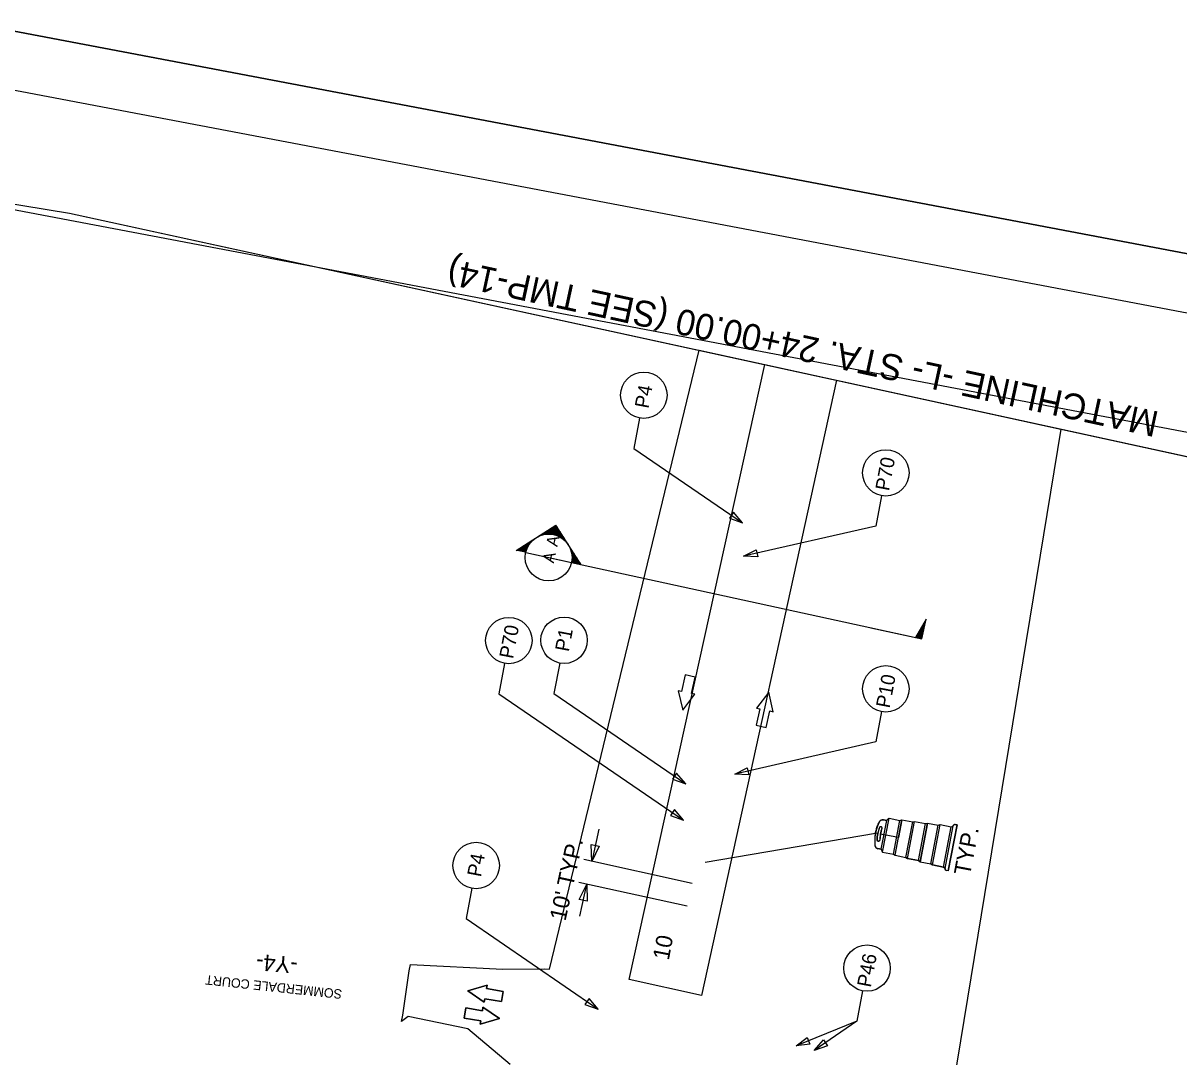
# Model space of a CAD drawing. Extents: x 1615680 to 1619687, y 899305 to 902270.
# Drawn here: x 1616156.6 to 1616649.2, y 900701 to 901141.7 of the extents above; entities that cross this region are included whole.
import ezdxf

# ---------------------------------------------------------------- set-up
doc = ezdxf.new("R2010")
doc.units = 0
for name, color, linetype in [('Default', 7, 'Continuous'), ('Prop Conc 2ft 6in Curb and Gutter', 7, 'Continuous'), ('Prop Conc 4in Sidewalk', 7, 'Continuous'), ('Prop Conc 5in Monolithic Keyed In Island', 7, 'Continuous'), ('Prop Conc Valley Gutter', 7, 'Continuous'), ('Prop Lane Arrow CELL', 7, 'Continuous'), ('Prop Mkg Solid Yel Skip RT Rpm 80ft', 7, 'Continuous'), ('Prop Shade Light', 7, 'Continuous'), ('Scratch_Level_5', 7, 'Continuous'), ('Scratch_Level_7', 7, 'Continuous'), ('Scratch_Level_8', 7, 'Continuous'), ('Stage 1', 7, 'Continuous'), ('Stage 5', 7, 'Continuous')]:
    doc.layers.add(name, color=color, linetype=linetype)

msp = doc.modelspace()

# ---------------------------------------------------------------- linework, layer by layer
at = {"layer": 'Default'}
for p, q in [((1616366.8, 900916.91), (1616383.64, 900927.73)), ((1616380.01, 900925.34), (1616379.7, 900923.91)), ((1616380.26, 900925.5), (1616379.91, 900923.91)), ((1616380.5, 900925.66), (1616380.12, 900923.91)), ((1616380.75, 900925.82), (1616380.34, 900923.91)), ((1616381, 900925.98), (1616380.55, 900923.91)), ((1616381.25, 900926.14), (1616380.76, 900923.91)), ((1616381.5, 900926.29), (1616380.98, 900923.91)), ((1616381.74, 900926.45), (1616381.19, 900923.91)), ((1616381.99, 900926.61), (1616381.4, 900923.89)), ((1616382.24, 900926.77), (1616381.61, 900923.87)), ((1616382.49, 900926.93), (1616381.81, 900923.85)), ((1616382.73, 900927.09), (1616382.02, 900923.82)), ((1616382.98, 900927.25), (1616382.23, 900923.8)), ((1616383.23, 900927.41), (1616382.44, 900923.77)), ((1616383.48, 900927.57), (1616382.65, 900923.75)), ((1616383.68, 900927.52), (1616382.85, 900923.72)), ((1616383.84, 900927.27), (1616383.06, 900923.68)), ((1616384, 900927.03), (1616383.26, 900923.63)), ((1616384.16, 900926.78), (1616383.46, 900923.59)), ((1616394.5, 900910.82), (1616383.64, 900927.73)), ((1616384.32, 900926.53), (1616383.67, 900923.54)), ((1616384.48, 900926.29), (1616383.87, 900923.5)), ((1616384.64, 900926.04), (1616384.07, 900923.46)), ((1616384.8, 900925.8), (1616384.25, 900923.29)), ((1616384.96, 900925.55), (1616384.44, 900923.17)), ((1616385.12, 900925.3), (1616384.63, 900923.07)), ((1616372.28, 900920.4), (1616372.01, 900919.16)), ((1616372.53, 900920.57), (1616372.32, 900919.6)), ((1616372.78, 900920.73), (1616372.63, 900920.03)), ((1616373.03, 900920.89), (1616372.92, 900920.37)), ((1616373.28, 900921.05), (1616373.19, 900920.66)), ((1616373.52, 900921.21), (1616373.47, 900920.95)), ((1616377.28, 900923.59), (1616377.24, 900923.4)), ((1616377.53, 900923.75), (1616377.48, 900923.51)), ((1616377.78, 900923.91), (1616377.72, 900923.62)), ((1616378.03, 900924.07), (1616377.94, 900923.69)), ((1616378.27, 900924.23), (1616378.17, 900923.73)), ((1616378.52, 900924.39), (1616378.39, 900923.77)), ((1616378.77, 900924.54), (1616378.61, 900923.82)), ((1616379.02, 900924.7), (1616378.83, 900923.86)), ((1616379.26, 900924.86), (1616379.06, 900923.91)), ((1616379.51, 900925.02), (1616379.27, 900923.91)), ((1616379.76, 900925.18), (1616379.48, 900923.91)), ((1616385.28, 900925.06), (1616384.82, 900922.97)), ((1616385.44, 900924.81), (1616385.01, 900922.88)), ((1616385.6, 900924.57), (1616385.21, 900922.78)), ((1616385.76, 900924.32), (1616385.4, 900922.68)), ((1616385.91, 900924.07), (1616385.59, 900922.58)), ((1616386.07, 900923.83), (1616385.78, 900922.47)), ((1616386.23, 900923.58), (1616385.96, 900922.33)), ((1616386.39, 900923.34), (1616386.14, 900922.19)), ((1616386.55, 900923.09), (1616386.33, 900922.05)), ((1616386.71, 900922.84), (1616386.51, 900921.91)), ((1616386.87, 900922.6), (1616386.69, 900921.77)), ((1616387.03, 900922.35), (1616386.88, 900921.63)), ((1616387.19, 900922.11), (1616387.06, 900921.49)), ((1616387.35, 900921.86), (1616387.24, 900921.35)), ((1616387.51, 900921.61), (1616387.42, 900921.2)), ((1616387.67, 900921.37), (1616387.6, 900921.06)), ((1616387.83, 900921.12), (1616387.78, 900920.91)), ((1616367.07, 900917.03), (1616367.03, 900916.86)), ((1616367.32, 900917.19), (1616367.24, 900916.81)), ((1616367.57, 900917.35), (1616367.44, 900916.77)), ((1616367.82, 900917.51), (1616367.64, 900916.73)), ((1616368.06, 900917.67), (1616367.85, 900916.68)), ((1616368.31, 900917.83), (1616368.05, 900916.64)), ((1616368.56, 900917.99), (1616368.26, 900916.59)), ((1616368.81, 900918.15), (1616368.46, 900916.55)), ((1616369.06, 900918.31), (1616368.66, 900916.5)), ((1616369.3, 900918.48), (1616368.87, 900916.46)), ((1616369.55, 900918.64), (1616369.07, 900916.42)), ((1616369.8, 900918.8), (1616369.27, 900916.37)), ((1616370.05, 900918.96), (1616369.48, 900916.33)), ((1616370.3, 900919.12), (1616369.68, 900916.28)), ((1616370.55, 900919.28), (1616369.88, 900916.24)), ((1616370.79, 900919.44), (1616370.09, 900916.19)), ((1616371.04, 900919.6), (1616370.29, 900916.15)), ((1616371.29, 900919.76), (1616370.49, 900916.11)), ((1616371.54, 900919.92), (1616370.7, 900916.06)), ((1616370.8, 900915.99), (1616390.34, 900911.73)), ((1616370.8, 900915.98), (1616388.4, 900912.15)), ((1616371.79, 900920.08), (1616371.25, 900917.61)), ((1616372.03, 900920.24), (1616371.68, 900918.61)), ((1616390.15, 900917.42), (1616390.1, 900917.18)), ((1616390.31, 900917.17), (1616390.24, 900916.84)), ((1616390.47, 900916.92), (1616390.36, 900916.43)), ((1616390.63, 900916.68), (1616390.49, 900916.02)), ((1616390.79, 900916.43), (1616390.59, 900915.51)), ((1616391.42, 900915.43), (1616390.62, 900911.75)), ((1616391.27, 900915.68), (1616390.68, 900912.97)), ((1616390.95, 900916.18), (1616390.69, 900914.97)), ((1616391.11, 900915.93), (1616390.78, 900914.43)), ((1616390.34, 900911.73), (1616539.62, 900879.2)), ((1616391.58, 900915.18), (1616390.83, 900911.7)), ((1616391.74, 900914.93), (1616391.03, 900911.65)), ((1616391.9, 900914.68), (1616391.23, 900911.61)), ((1616392.06, 900914.43), (1616391.43, 900911.56)), ((1616392.22, 900914.18), (1616391.64, 900911.51)), ((1616392.38, 900913.93), (1616391.84, 900911.46)), ((1616392.54, 900913.68), (1616392.04, 900911.42)), ((1616392.69, 900913.43), (1616392.25, 900911.37)), ((1616392.85, 900913.18), (1616392.45, 900911.32)), ((1616393.01, 900912.93), (1616392.65, 900911.28)), ((1616393.17, 900912.69), (1616392.85, 900911.23)), ((1616393.33, 900912.44), (1616393.06, 900911.18)), ((1616393.49, 900912.19), (1616393.26, 900911.14)), ((1616393.65, 900911.94), (1616393.46, 900911.09)), ((1616393.81, 900911.69), (1616393.67, 900911.04)), ((1616393.97, 900911.44), (1616393.87, 900910.99)), ((1616394.12, 900911.19), (1616394.07, 900910.95)), ((1616541.43, 900887.52), (1616536.99, 900879.78)), ((1616539.62, 900879.2), (1616541.43, 900887.52)), ((1616541.04, 900885.79), (1616540.56, 900885.9)), ((1616541.09, 900885.99), (1616540.67, 900886.09)), ((1616541.13, 900886.2), (1616540.78, 900886.27)), ((1616541.18, 900886.4), (1616540.89, 900886.46)), ((1616541.22, 900886.61), (1616541, 900886.65)), ((1616541.26, 900886.81), (1616541.1, 900886.84)), ((1616541.31, 900887.01), (1616541.21, 900887.03)), ((1616517.94, 900883.93), (1616539.62, 900879.2)), ((1616539.89, 900880.5), (1616537.75, 900880.97)), ((1616539.93, 900880.7), (1616537.86, 900881.16)), ((1616539.98, 900880.91), (1616537.96, 900881.35)), ((1616540.02, 900881.11), (1616538.07, 900881.54)), ((1616540.07, 900881.31), (1616538.18, 900881.72)), ((1616540.11, 900881.52), (1616538.29, 900881.91)), ((1616540.16, 900881.72), (1616538.4, 900882.1)), ((1616540.2, 900881.92), (1616538.51, 900882.29)), ((1616540.24, 900882.13), (1616538.61, 900882.48)), ((1616540.29, 900882.33), (1616538.72, 900882.67)), ((1616540.33, 900882.53), (1616538.83, 900882.86)), ((1616540.38, 900882.74), (1616538.94, 900883.05)), ((1616540.42, 900882.94), (1616539.05, 900883.24)), ((1616540.47, 900883.14), (1616539.16, 900883.43)), ((1616540.51, 900883.35), (1616539.26, 900883.62)), ((1616540.56, 900883.55), (1616539.37, 900883.81)), ((1616540.6, 900883.76), (1616539.48, 900884)), ((1616540.64, 900883.96), (1616539.59, 900884.19)), ((1616540.69, 900884.16), (1616539.7, 900884.38)), ((1616540.73, 900884.37), (1616539.81, 900884.57)), ((1616540.78, 900884.57), (1616539.91, 900884.76)), ((1616540.82, 900884.77), (1616540.02, 900884.95)), ((1616540.87, 900884.98), (1616540.13, 900885.14)), ((1616540.91, 900885.18), (1616540.24, 900885.33)), ((1616540.95, 900885.38), (1616540.35, 900885.52)), ((1616541, 900885.59), (1616540.45, 900885.71)), ((1616539.62, 900879.28), (1616537.1, 900879.83)), ((1616539.67, 900879.48), (1616537.21, 900880.02)), ((1616539.71, 900879.69), (1616537.31, 900880.21)), ((1616539.76, 900879.89), (1616537.42, 900880.4)), ((1616539.8, 900880.09), (1616537.53, 900880.59)), ((1616539.85, 900880.3), (1616537.64, 900880.78)), ((1616511.96, 900716.19), (1616493.77, 900703.78))]:
    msp.add_line(p, q, dxfattribs=at)
for points in [[(1616419.31, 900973.34), (1616416.85, 900960.4), (1616463.25, 900928.63)], [(1616522.44, 900940.23), (1616519.98, 900927.29), (1616463.69, 900914.4)], [(1616361.77, 900868.76), (1616359.32, 900855.81), (1616438.12, 900801.85)], [(1616385.29, 900868.87), (1616382.83, 900855.93), (1616439.03, 900817.45)], [(1616522.45, 900848.18), (1616520, 900835.24), (1616459.86, 900821.46)], [(1616347.84, 900772.86), (1616345.38, 900759.92), (1616401.72, 900721.34)], [(1616514.41, 900729.13), (1616511.96, 900716.19), (1616486, 900705.66)]]:
    msp.add_lwpolyline(points, dxfattribs=at)
for points in [[(1616457.59, 900930.62), (1616463.25, 900928.63), (1616459.34, 900933.18)], [(1616469.69, 900914.18), (1616463.69, 900914.4), (1616468.99, 900917.2)], [(1616433.37, 900819.44), (1616439.03, 900817.45), (1616435.12, 900822)], [(1616465.86, 900821.24), (1616459.86, 900821.46), (1616465.16, 900824.27)], [(1616432.46, 900803.85), (1616438.12, 900801.85), (1616434.22, 900806.41)], [(1616396.06, 900723.33), (1616401.72, 900721.34), (1616397.81, 900725.9)], [(1616491.95, 900706.4), (1616486, 900705.66), (1616490.78, 900709.28)], [(1616499.43, 900705.76), (1616493.77, 900703.78), (1616497.68, 900708.33)]]:
    msp.add_lwpolyline(points, close=True, dxfattribs=at)
for centre, radius in [((1616421.16, 900983.06), 9.89), ((1616524.28, 900949.95), 9.89), ((1616380.57, 900913.86), 10), ((1616363.62, 900878.48), 9.89), ((1616387.14, 900878.59), 9.89), ((1616524.3, 900857.9), 9.89), ((1616349.69, 900782.58), 9.89), ((1616516.26, 900738.85), 9.89)]:
    msp.add_circle(centre, radius, dxfattribs=at)
at = {"layer": 'Prop Conc 4in Sidewalk'}
msp.add_lwpolyline([(1616176.29, 901060.7), (1616848.46, 900914.27), (1616896.28, 900812.91), (1616872.94, 900688.21), (1616835.87, 900695.21), (1616753.94, 900262.18), (1616898.09, 900233.43), (1616734.79, 899562.1), (1616202.98, 899609.43), (1616198.71, 899647.14), (1615822.69, 899825.07), (1616054.34, 901080.76)], close=True, dxfattribs=at)
at = {"layer": 'Prop Conc 5in Monolithic Keyed In Island'}
for p, q in [((1616438.74, 900863.83), (1616437.24, 900856.79)), ((1616442.99, 900862.92), (1616438.74, 900863.83)), ((1616441.49, 900855.88), (1616442.99, 900862.92)), ((1616437.24, 900856.79), (1616435.8, 900857.1)), ((1616435.8, 900857.1), (1616437.75, 900848.75)), ((1616474.41, 900856.51), (1616469.18, 900849.72)), ((1616476.31, 900848.15), (1616474.41, 900856.51)), ((1616437.75, 900848.75), (1616442.94, 900855.57)), ((1616442.94, 900855.57), (1616441.49, 900855.88)), ((1616470.62, 900849.4), (1616469.07, 900842.37)), ((1616469.18, 900849.72), (1616470.62, 900849.4)), ((1616473.32, 900841.44), (1616474.87, 900848.47)), ((1616474.87, 900848.47), (1616476.31, 900848.15)), ((1616469.07, 900842.37), (1616473.32, 900841.44)), ((1616354.32, 900731.54), (1616346.09, 900729.18)), ((1616346.09, 900729.18), (1616354.32, 900731.54)), ((1616346.09, 900729.18), (1616353.16, 900724.33)), ((1616353.16, 900724.33), (1616346.09, 900729.18)), ((1616354.09, 900730.08), (1616354.32, 900731.54)), ((1616354.32, 900731.54), (1616354.09, 900730.08)), ((1616361.19, 900728.93), (1616354.09, 900730.08)), ((1616354.09, 900730.08), (1616361.19, 900728.93)), ((1616360.5, 900724.64), (1616361.19, 900728.93)), ((1616361.19, 900728.93), (1616360.5, 900724.64)), ((1616353.16, 900724.33), (1616353.39, 900725.79)), ((1616353.39, 900725.79), (1616353.16, 900724.33)), ((1616353.39, 900725.79), (1616360.5, 900724.64)), ((1616360.5, 900724.64), (1616353.39, 900725.79)), ((1616345.24, 900721.84), (1616344.54, 900717.55)), ((1616344.54, 900717.55), (1616345.24, 900721.84)), ((1616352.34, 900720.69), (1616345.24, 900721.84)), ((1616345.24, 900721.84), (1616352.34, 900720.69)), ((1616352.58, 900722.15), (1616352.34, 900720.69)), ((1616352.34, 900720.69), (1616352.58, 900722.15)), ((1616359.65, 900717.3), (1616352.58, 900722.15)), ((1616352.58, 900722.15), (1616359.65, 900717.3)), ((1616344.54, 900717.55), (1616351.65, 900716.4)), ((1616351.65, 900716.4), (1616344.54, 900717.55)), ((1616351.41, 900714.94), (1616359.65, 900717.3)), ((1616359.65, 900717.3), (1616351.41, 900714.94)), ((1616351.65, 900716.4), (1616351.41, 900714.94)), ((1616351.41, 900714.94), (1616351.65, 900716.4))]:
    msp.add_line(p, q, dxfattribs=at)
at = {"layer": 'Prop Conc Valley Gutter'}
msp.add_lwpolyline([(1616364.12, 900697.77), (1616346.17, 900712.92), (1616320.68, 900718.26), (1616317.92, 900716.06), (1616318.38, 900718.79), (1616321.17, 900737.64), (1616321.64, 900740.44), (1616360.99, 900738.34), (1616378.95, 900738.53), (1616380.95, 900738.45), (1616444.67, 901002.24), (1616598.93, 900968.63), (1616553.12, 900689.68), (1616549.22, 900671.08), (1616523.49, 900664.4), (1616517.29, 900664.94), (1616514.38, 900663.18), (1616513.71, 900663.29), (1616502.01, 900665.64), (1616409.34, 900449.1), (1616407.45, 900435.71), (1616394.68, 900360.06), (1616392.05, 900350.44), (1616393.93, 900269.36)], dxfattribs=at)
msp.add_lwpolyline([(1616503.23, 900989.48), (1616445.68, 900727.11), (1616414.96, 900733.92), (1616472.65, 900996.14)], close=True, dxfattribs=at)
at = {"layer": 'Prop Lane Arrow CELL'}
msp.add_line((1616176.29, 901060.7), (1616775.18, 900930.23), dxfattribs=at)
at = {"layer": 'Prop Mkg Solid Yel Skip RT Rpm 80ft'}
for p, q in [((1616401.93, 900798), (1616398.94, 900784.33)), ((1616441.74, 900774.97), (1616395.52, 900785.08)), ((1616439.6, 900765.2), (1616393.38, 900775.31)), ((1616393.82, 900760.92), (1616396.8, 900774.56))]:
    msp.add_line(p, q, dxfattribs=at)
for points in [[(1616402.14, 900790.79), (1616398.94, 900784.33), (1616398.72, 900791.54)], [(1616393.6, 900768.09), (1616396.8, 900774.56), (1616397.01, 900767.35)]]:
    msp.add_lwpolyline(points, close=True, dxfattribs=at)
at = {"layer": 'Prop Shade Light'}
msp.add_line((1616447.29, 900783.99), (1616519.86, 900796.34), dxfattribs=at)
at = {"layer": 'Scratch_Level_5'}
for p, q in [((1616522.93, 900788.3), (1616525.66, 900802.7)), ((1616524.7, 900801.8), (1616523.26, 900802.08)), ((1616525.66, 900802.7), (1616530.28, 900801.82)), ((1616522.21, 900799.08), (1616522.15, 900799.1)), ((1616522.36, 900789.49), (1616524.7, 900801.8)), ((1616527.55, 900787.42), (1616530.28, 900801.82)), ((1616528.25, 900786.93), (1616531.12, 900802.03)), ((1616530.28, 900801.82), (1616531.12, 900802.03)), ((1616531.12, 900802.03), (1616535.74, 900801.15)), ((1616532.87, 900786.05), (1616535.74, 900801.15)), ((1616533.57, 900785.56), (1616536.57, 900801.35)), ((1616535.74, 900801.15), (1616536.57, 900801.35)), ((1616536.57, 900801.35), (1616541.19, 900800.47)), ((1616538.19, 900784.68), (1616541.19, 900800.47)), ((1616538.89, 900784.18), (1616542.03, 900800.68)), ((1616541.19, 900800.47), (1616542.03, 900800.68)), ((1616542.03, 900800.68), (1616546.64, 900799.8)), ((1616543.51, 900783.31), (1616546.64, 900799.8)), ((1616544.22, 900782.81), (1616547.48, 900800)), ((1616546.64, 900799.8), (1616547.48, 900800)), ((1616547.48, 900800), (1616552.1, 900799.13)), ((1616548.83, 900781.94), (1616552.1, 900799.13)), ((1616549.52, 900781.34), (1616552.95, 900799.43)), ((1616550.91, 900780.28), (1616554.64, 900799.91)), ((1616552.1, 900799.13), (1616552.93, 900799.33)), ((1616554.64, 900799.91), (1616553.87, 900800.05)), ((1616521.05, 900792.93), (1616520.98, 900792.94)), ((1616522.36, 900789.49), (1616520.92, 900789.76)), ((1616522.93, 900788.3), (1616527.55, 900787.42)), ((1616527.55, 900787.42), (1616528.25, 900786.93)), ((1616528.25, 900786.93), (1616532.87, 900786.05)), ((1616532.87, 900786.05), (1616533.57, 900785.56)), ((1616533.57, 900785.56), (1616538.19, 900784.68)), ((1616538.19, 900784.68), (1616538.89, 900784.18)), ((1616538.89, 900784.18), (1616543.51, 900783.31)), ((1616543.51, 900783.31), (1616544.22, 900782.81)), ((1616544.22, 900782.81), (1616548.83, 900781.94)), ((1616548.84, 900781.94), (1616549.54, 900781.44)), ((1616550.91, 900780.28), (1616550.14, 900780.42))]:
    msp.add_line(p, q, dxfattribs=at)
for points in [[(1616531.12, 900802.03), (1616529.68, 900794.48), (1616521.98, 900795.94), (1616522.11, 900796.58), (1616522.23, 900797.03), (1616522.33, 900797.41), (1616522.43, 900797.73), (1616522.53, 900798.08), (1616522.63, 900798.37), (1616522.67, 900798.51), (1616522.66, 900798.64), (1616522.6, 900798.79), (1616522.51, 900798.92), (1616522.4, 900799.02), (1616522.29, 900799.07), (1616522.15, 900799.1), (1616521.97, 900799.11), (1616521.8, 900799.05), (1616521.7, 900798.99), (1616521.62, 900798.9), (1616521.57, 900798.83), (1616521.53, 900798.74), (1616521.45, 900798.49), (1616521.36, 900798.23), (1616521.28, 900797.98), (1616521.2, 900797.71), (1616521.11, 900797.37), (1616521.01, 900797), (1616520.95, 900796.71), (1616520.89, 900796.46), (1616520.83, 900796.16), (1616519.86, 900796.34), (1616519.95, 900796.79), (1616520.04, 900797.14), (1616520.16, 900797.63), (1616520.25, 900797.96), (1616520.36, 900798.33), (1616520.49, 900798.74), (1616520.66, 900799.22), (1616520.85, 900799.69), (1616521.08, 900800.24), (1616521.29, 900800.69), (1616521.48, 900801.09), (1616521.58, 900801.27), (1616521.67, 900801.43), (1616521.8, 900801.59), (1616521.96, 900801.75), (1616522.11, 900801.84), (1616522.29, 900801.95), (1616522.46, 900802.02), (1616522.67, 900802.08), (1616522.84, 900802.1), (1616523.04, 900802.11), (1616523.19, 900802.09), (1616523.26, 900802.08), (1616524.7, 900801.8), (1616524.88, 900802.06), (1616525, 900802.19), (1616525.13, 900802.32), (1616525.28, 900802.45), (1616525.48, 900802.59), (1616525.59, 900802.66), (1616525.66, 900802.7), (1616530.28, 900801.82)], [(1616532.87, 900786.05), (1616535.74, 900801.15), (1616536.57, 900801.35), (1616541.19, 900800.47), (1616542.03, 900800.68), (1616538.89, 900784.18), (1616538.19, 900784.68), (1616533.57, 900785.56)], [(1616543.51, 900783.31), (1616546.64, 900799.8), (1616547.48, 900800), (1616552.1, 900799.13), (1616552.93, 900799.33), (1616552.97, 900799.52), (1616553.02, 900799.63), (1616553.11, 900799.77), (1616553.21, 900799.89), (1616553.31, 900799.95), (1616553.44, 900800.02), (1616553.58, 900800.05), (1616553.7, 900800.07), (1616553.8, 900800.07), (1616553.87, 900800.05), (1616554.64, 900799.91), (1616550.91, 900780.28), (1616550.14, 900780.42), (1616550.03, 900780.45), (1616549.92, 900780.5), (1616549.81, 900780.57), (1616549.73, 900780.65), (1616549.66, 900780.72), (1616549.58, 900780.85), (1616549.54, 900780.98), (1616549.51, 900781.13), (1616549.5, 900781.21), (1616549.52, 900781.34), (1616549.54, 900781.44), (1616548.84, 900781.94), (1616544.22, 900782.81)], [(1616528.25, 900786.93), (1616529.68, 900794.48), (1616521.98, 900795.94), (1616521.91, 900795.56), (1616521.87, 900795.27), (1616521.83, 900794.98), (1616521.79, 900794.67), (1616521.76, 900794.33), (1616521.73, 900793.98), (1616521.7, 900793.6), (1616521.69, 900793.35), (1616521.64, 900793.22), (1616521.56, 900793.11), (1616521.46, 900793.01), (1616521.35, 900792.96), (1616521.23, 900792.92), (1616521.12, 900792.92), (1616520.91, 900792.96), (1616520.8, 900793.01), (1616520.69, 900793.1), (1616520.6, 900793.22), (1616520.54, 900793.38), (1616520.53, 900793.5), (1616520.55, 900793.78), (1616520.57, 900794.17), (1616520.65, 900794.96), (1616520.72, 900795.52), (1616520.79, 900795.94), (1616520.83, 900796.16), (1616519.86, 900796.34), (1616519.79, 900795.94), (1616519.71, 900795.42), (1616519.64, 900794.88), (1616519.6, 900794.31), (1616519.57, 900793.77), (1616519.55, 900793.17), (1616519.56, 900792.48), (1616519.58, 900792.08), (1616519.62, 900791.41), (1616519.65, 900791.13), (1616519.68, 900790.95), (1616519.74, 900790.75), (1616519.83, 900790.55), (1616519.99, 900790.32), (1616520.14, 900790.15), (1616520.3, 900790.03), (1616520.48, 900789.91), (1616520.67, 900789.83), (1616520.92, 900789.76), (1616522.36, 900789.49), (1616522.39, 900789.34), (1616522.44, 900789.18), (1616522.52, 900788.97), (1616522.62, 900788.76), (1616522.73, 900788.58), (1616522.93, 900788.3), (1616527.55, 900787.42)]]:
    msp.add_lwpolyline(points, close=True, dxfattribs=at)
for centre, radius, start, end in [((1616522.97, 900800.54), 1.57, 79.2494, 152.3001), ((1616526.97, 900800.33), 2.71, 118.7358, 146.9434), ((1616537.24, 900793.04), 17.69, 152.3001, 186.1986), ((1616538.21, 900792.86), 17.69, 160.5754, 177.9234), ((1616522.05, 900798.56), 0.548, 79.2494, 160.5754), ((1616539.37, 900792.64), 17.69, 161.1006, 177.3981), ((1616522.11, 900798.55), 0.548, 341.1006, 79.2494), ((1616553.72, 900799.28), 0.783, 79.2494, 169.2494), ((1616521.08, 900793.48), 0.548, 177.9234, 259.2494), ((1616521.15, 900793.47), 0.548, 259.2494, 357.3981), ((1616521.21, 900791.3), 1.57, 186.1986, 259.2494), ((1616525.01, 900790.03), 2.71, 191.5554, 219.7629), ((1616550.29, 900781.19), 0.783, 169.2494, 259.2494)]:
    msp.add_arc(centre, radius, start, end, dxfattribs=at)
at = {"layer": 'Scratch_Level_7'}
msp.add_lwpolyline([(1616014.55, 901139.21), (1615734.74, 899665.53), (1616766.32, 899469.67), (1617046.12, 900943.35)], close=True, dxfattribs=at)
at = {"layer": 'Scratch_Level_8'}
msp.add_lwpolyline([(1616054.34, 901080.76), (1615793.19, 899705.33), (1616726.52, 899528.12), (1616890.46, 900391.55), (1616774.26, 900413.61), (1616871.48, 900925.61)], close=True, dxfattribs=at)
at = {"layer": 'Stage 5'}
for points in [[(1616760.47, 899304.87), (1615679.78, 899510.06), (1615994.65, 901168.43), (1617075.34, 900963.24)], [(1616760.47, 899304.87), (1617075.34, 900963.24), (1615994.65, 901168.43), (1615679.78, 899510.06)]]:
    msp.add_lwpolyline(points, close=True, dxfattribs=at)

# ---------------------------------------------------------------- texts
at = {"layer": 'Default'}
for s, height, rotation, p in [('P4', 6, 79.2493, (1616423.08, 900977.14)), ('P70', 6, 79.2493, (1616525.62, 900941.99)), ('A', 5, 77.7132, (1616384.26, 900918.24)), ('A', 5, 77.7132, (1616382.74, 900911.25)), ('P70', 6, 79.2494, (1616365.35, 900870.44)), ('P1', 6, 79.2493, (1616389.13, 900873.44)), ('P10', 6, 79.2494, (1616525.89, 900849.4)), ('TYP.', 7, 79.2494, (1616560.12, 900777.98)), ('P4', 6, 79.2493, (1616351.68, 900777.43)), ('P46', 6, 79.2494, (1616517.85, 900730.36)), ('SOMMERDALE COURT', 4, 173.9042, (1616292.69, 900729.65))]:
    msp.add_text(s, height=height, rotation=rotation, dxfattribs=at).set_placement(p)
at = {"layer": 'Prop Conc 2ft 6in Curb and Gutter'}
for s, rotation, p in [('10', 79.16, (1616431.76, 900741.92)), ('-Y4-', 175.0178, (1616273.8, 900743.4))]:
    msp.add_text(s, height=7, rotation=rotation, dxfattribs=at).set_placement(p)
at = {"layer": 'Prop Mkg Solid Yel Skip RT Rpm 80ft'}
msp.add_text("10' TYP.", height=7, rotation=77.6625, dxfattribs=at).set_placement((1616387.74, 900758.67))
at = {"layer": 'Stage 1'}
msp.add_text('MATCHLINE -L- STA. 24+00.00 (SEE TMP-14)', height=11, rotation=167.7956, dxfattribs=at).set_placement((1616641.18, 900975.9))

doc.saveas('drawing.dxf')
